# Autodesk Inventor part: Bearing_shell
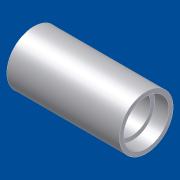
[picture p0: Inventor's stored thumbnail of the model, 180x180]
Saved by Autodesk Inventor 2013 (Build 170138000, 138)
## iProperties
Shininess: 64.0
Length Units: 11269
Angle Units: 11279
Time Units: 11290
Mass Units: 11283
Length Display Precision: 3
Angle Display Precision: 2
Compacted: True
Part Number: Bearing_shell
Document SubType Name: Modeling
Created: 2002-10
Designer: roithn
Density: 1 g/cm^3
Material: Generic
Density: 0.0
Volumn: 0.0
Area: 0.0
PropertySet Name: Model Information
Control State: 0
Master: False
Checked Out: False
Author: roithn
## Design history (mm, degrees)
sketch "Sketch1"
  geometry: L1 (1425.037, 192.54)-(1435.037, 192.54); L2 (1435.037, 192.54)-(1435.037, 189.54); L3 (1435.037, 189.54)-(1494.637, 189.54); L4 (1494.637, 189.54)-(1494.637, 192.54); L5 (1494.637, 192.54)-(1504.637, 192.54); L6 (1504.637, 192.54)-(1504.637, 195.54); L7 (1504.637, 195.54)-(1425.037, 195.54); L8 (1425.037, 195.54)-(1425.037, 192.54); L9 (1425.037, 176.54)-(1504.637, 176.54)
  constraints: 18 end point
revolve "Revolution1" sketch "Sketch1" stored, may be unused: angle "d0" = 90 deg
body "Solid1"
